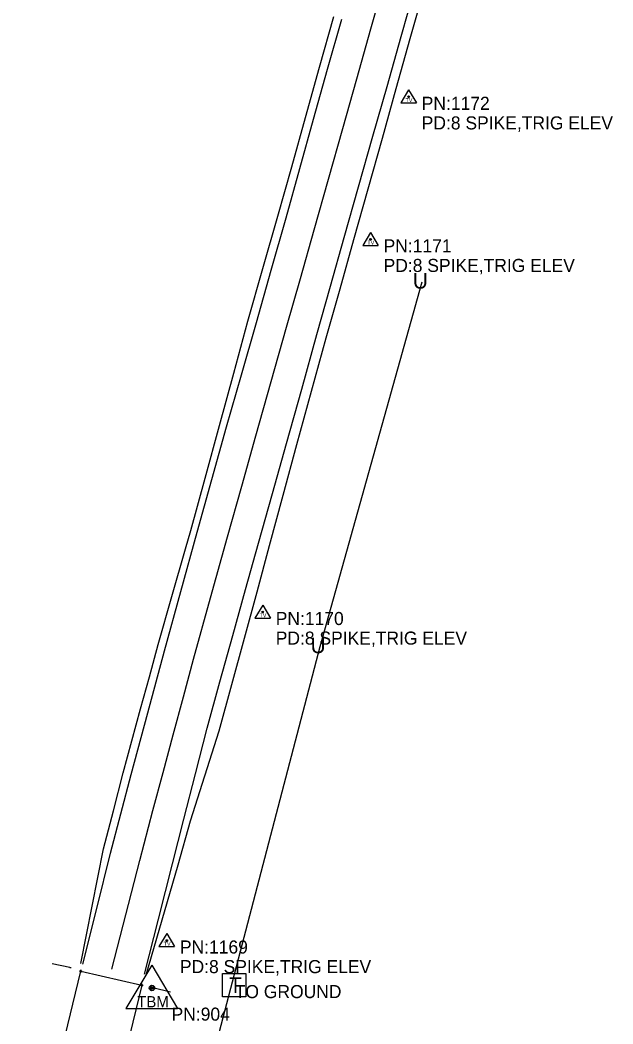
# Model space of a CAD drawing. Extents: x 1445297 to 1476720, y 2042269 to 2057889.
# Drawn here: x 1445820.8 to 1446047.7, y 2054654 to 2055038.2 of the extents above; entities that cross this region are included whole.
import ezdxf

# ---------------------------------------------------------------- set-up
doc = ezdxf.new("R2010")
doc.units = 0
for name, color, linetype in [('S_BRIDGE', 7, 'Continuous'), ('S_EDGE_PAVEMENT', 7, 'Continuous'), ('S_PAVEMENT_CROWN', 7, 'Continuous'), ('S_PRIMARY_CTL', 7, 'Continuous'), ('S_PRIMARY_CTL_ANNOT', 7, 'Continuous'), ('S_SECONDARY_CTL', 7, 'Continuous'), ('S_SECONDARY_CTL_ANNOT', 7, 'Continuous'), ('S_SHOULDER', 7, 'Continuous'), ('S_STR_PT_SYM', 7, 'Continuous'), ('S_TELEPHONE_UTILITIES', 7, 'Continuous'), ('S_TELEPHONE_UTILITIES_ANNOT', 7, 'Continuous'), ('S_UNDERGROUND_CABLE', 7, 'Continuous'), ('S_UTL_PT_SYM', 7, 'Continuous'), ('S_WALL', 7, 'Continuous')]:
    doc.layers.add(name, color=color, linetype=linetype)

msp = doc.modelspace()

# ---------------------------------------------------------------- linework, layer by layer
at = {"layer": 'S_BRIDGE'}
for p, q in [((1445820.81, 2054577.05), (1445844.02, 2054674.24)), ((1445844.02, 2054674.24), (1445867.36, 2054668.87)), ((1445867.36, 2054668.87), (1445844.01, 2054571.43))]:
    msp.add_line(p, q, dxfattribs=at)
at = {"layer": 'S_EDGE_PAVEMENT'}
for points in [[(1445868.42, 2054673), (1445873.8, 2054694.15), (1445879.18, 2054715.3), (1445883.43, 2054732.32), (1445887.92, 2054749.76), (1445892.4, 2054767.2), (1445897.32, 2054784.9), (1445902.23, 2054802.61), (1445907.14, 2054820.31), (1445912.06, 2054838.01), (1445917.42, 2054857.06), (1445922.78, 2054876.11), (1445928.6, 2054897), (1445934.41, 2054917.89), (1445939.66, 2054936.42), (1445944.91, 2054954.95), (1445950.38, 2054974.34), (1445955.85, 2054993.73), (1445961.24, 2055012.84), (1445966.63, 2055031.96), (1445972, 2055050.98)], [(1445844.89, 2054676.9), (1445850.15, 2054698.12), (1445855.4, 2054719.34), (1445859.33, 2054734.41), (1445863.27, 2054749.48), (1445869.68, 2054773.13), (1445876.1, 2054796.78), (1445882.33, 2054819.51), (1445888.57, 2054842.24), (1445894.2, 2054862.4), (1445899.83, 2054882.56), (1445905.54, 2054902.48), (1445911.24, 2054922.4), (1445916.92, 2054942.47), (1445922.59, 2054962.55), (1445927.86, 2054981.39), (1445933.14, 2055000.23), (1445938.52, 2055019.41), (1445943.91, 2055038.59)]]:
    msp.add_lwpolyline(points, dxfattribs=at)
at = {"layer": 'S_PAVEMENT_CROWN'}
msp.add_lwpolyline([(1445855.91, 2054675.01), (1445861.26, 2054695.81), (1445866.61, 2054716.61), (1445871.67, 2054735.74), (1445875.56, 2054750.21), (1445879.46, 2054764.68), (1445883.35, 2054779.16), (1445887.24, 2054793.63), (1445893.7, 2054817.03), (1445900.17, 2054840.42), (1445905.62, 2054859.76), (1445911.06, 2054879.11), (1445916.95, 2054899.9), (1445922.84, 2054920.69), (1445928.1, 2054939.34), (1445933.36, 2054957.99), (1445938.82, 2054977.34), (1445944.28, 2054996.69), (1445949.66, 2055015.74), (1445955.04, 2055034.8), (1445960.36, 2055053.8)], dxfattribs=at)
at = {"layer": 'S_PRIMARY_CTL'}
for p, q in [((1445871.29, 2054676.45), (1445861.26, 2054659.94)), ((1445871.29, 2054676.45), (1445881.11, 2054659.94)), ((1445861.26, 2054659.94), (1445881.11, 2054659.94))]:
    msp.add_line(p, q, dxfattribs=at)
for radius in [1.04, 0.609, 0.344]:
    msp.add_circle((1445871.29, 2054667.75), radius, dxfattribs=at)
at = {"layer": 'S_SECONDARY_CTL'}
for p, q in [((1445969.53, 2055011.46), (1445966.52, 2055006.51)), ((1445969.53, 2055011.46), (1445972.48, 2055006.51)), ((1445966.52, 2055006.51), (1445972.48, 2055006.51)), ((1445954.94, 2054956.91), (1445951.93, 2054951.96)), ((1445954.94, 2054956.91), (1445957.89, 2054951.96)), ((1445951.93, 2054951.96), (1445957.89, 2054951.96)), ((1445913.66, 2054814.28), (1445910.65, 2054809.33)), ((1445913.66, 2054814.28), (1445916.61, 2054809.33)), ((1445910.65, 2054809.33), (1445916.61, 2054809.33)), ((1445876.98, 2054688.55), (1445873.97, 2054683.6)), ((1445876.98, 2054688.55), (1445879.93, 2054683.6)), ((1445873.97, 2054683.6), (1445879.93, 2054683.6))]:
    msp.add_line(p, q, dxfattribs=at)
for centre, radius in [((1445969.53, 2055008.85), 0.311), ((1445969.53, 2055008.85), 0.183), ((1445969.53, 2055008.85), 0.103), ((1445954.94, 2054954.3), 0.311), ((1445954.94, 2054954.3), 0.183), ((1445954.94, 2054954.3), 0.103), ((1445913.66, 2054811.67), 0.311), ((1445913.66, 2054811.67), 0.183), ((1445913.66, 2054811.67), 0.103), ((1445876.98, 2054685.94), 0.311), ((1445876.98, 2054685.94), 0.183), ((1445876.98, 2054685.94), 0.103)]:
    msp.add_circle(centre, radius, dxfattribs=at)
at = {"layer": 'S_SHOULDER'}
for points in [[(1445869.12, 2054672.84), (1445875.24, 2054693.88), (1445881.35, 2054714.93), (1445886.02, 2054731.75), (1445891.55, 2054748.94), (1445897.07, 2054766.13), (1445901.88, 2054783.86), (1445906.68, 2054801.6), (1445911.49, 2054819.33), (1445916.29, 2054837.07), (1445921.52, 2054856.42), (1445926.74, 2054875.78), (1445932.37, 2054896.18), (1445938, 2054916.58), (1445943.3, 2054935.38), (1445948.6, 2054954.19), (1445954.03, 2054973.6), (1445959.46, 2054993.01), (1445964.77, 2055012.06), (1445970.08, 2055031.1), (1445975.49, 2055050.1)], [(1445844.07, 2054677.1), (1445848.4, 2054699.06), (1445852.73, 2054721.02), (1445856.51, 2054735.58), (1445860.29, 2054750.14), (1445863.63, 2054762.4), (1445866.96, 2054774.66), (1445870.3, 2054786.91), (1445873.64, 2054799.17), (1445878.88, 2054817.53), (1445884.12, 2054835.89), (1445886.15, 2054842.8), (1445891.63, 2054862.92), (1445897.1, 2054883.04), (1445902.57, 2054903.02), (1445908.04, 2054922.99), (1445913.77, 2054943.1), (1445919.49, 2054963.22), (1445924.78, 2054982.04), (1445930.06, 2055000.86), (1445935.44, 2055020.19), (1445940.83, 2055039.53)]]:
    msp.add_lwpolyline(points, dxfattribs=at)
at = {"layer": 'S_STR_PT_SYM'}
for points in [[(1445844.02, 2054674.24), (1445844.02, 2054674.74), (1445844.02, 2054674.24), (1445843.52, 2054674.24), (1445844.02, 2054674.24), (1445844.02, 2054673.74), (1445844.02, 2054674.24), (1445844.52, 2054674.24)], [(1445867.36, 2054668.87), (1445867.36, 2054669.37), (1445867.36, 2054668.87), (1445866.86, 2054668.87), (1445867.36, 2054668.87), (1445867.36, 2054668.37), (1445867.36, 2054668.87), (1445867.86, 2054668.87)]]:
    msp.add_lwpolyline(points, dxfattribs=at)
at = {"layer": 'S_TELEPHONE_UTILITIES'}
msp.add_lwpolyline([(1445898.23, 2054664.36), (1445898.23, 2054673.36), (1445907.23, 2054673.36), (1445907.23, 2054664.36)], close=True, dxfattribs=at)
at = {"layer": 'S_UNDERGROUND_CABLE'}
for p, q in [((1445935.62, 2054798.44), (1445974.75, 2054937.98)), ((1445870.09, 2054547.32), (1445935.62, 2054798.44))]:
    msp.add_line(p, q, dxfattribs=at)
at = {"layer": 'S_WALL'}
for points in [[(1445840.34, 2054675.43), (1445839.99, 2054675.52), (1445839.81, 2054675.54), (1445833.07, 2054676.94)], [(1445871.03, 2054668.15), (1445871.46, 2054668.1), (1445871.64, 2054667.94), (1445878.42, 2054666.24)]]:
    msp.add_lwpolyline(points, dxfattribs=at)

# ---------------------------------------------------------------- texts
at = {"layer": 'S_PRIMARY_CTL'}
msp.add_text('TBM', height=4.287, dxfattribs=at).set_placement((1445865.64, 2054660.36))
at = {"layer": 'S_PRIMARY_CTL_ANNOT'}
msp.add_text('PN:904', height=5, dxfattribs=at).set_placement((1445878.79, 2054655.25))
at = {"layer": 'S_SECONDARY_CTL'}
for p in [(1445968.33, 2055006.84), (1445953.74, 2054952.29), (1445912.46, 2054809.66), (1445875.78, 2054683.93)]:
    msp.add_text('TV', height=1.5, dxfattribs=at).set_placement(p)
at = {"layer": 'S_SECONDARY_CTL_ANNOT'}
for s, p in [('PN:1172', (1445974.53, 2055003.85)), ('PD:8 SPIKE,TRIG ELEV', (1445974.53, 2054996.35)), ('PN:1171', (1445959.94, 2054949.3)), ('PD:8 SPIKE,TRIG ELEV', (1445959.94, 2054941.8)), ('PN:1170', (1445918.66, 2054806.67)), ('PD:8 SPIKE,TRIG ELEV', (1445918.66, 2054799.17)), ('PN:1169', (1445881.98, 2054680.94)), ('PD:8 SPIKE,TRIG ELEV', (1445881.98, 2054673.44))]:
    msp.add_text(s, height=5, dxfattribs=at).set_placement(p)
at = {"layer": 'S_TELEPHONE_UTILITIES'}
msp.add_text('T', height=6, dxfattribs=at).set_placement((1445900.8, 2054665.86))
at = {"layer": 'S_TELEPHONE_UTILITIES_ANNOT'}
msp.add_text('TO GROUND', height=5, dxfattribs=at).set_placement((1445902.96, 2054663.88))
at = {"layer": 'S_UTL_PT_SYM'}
for p in [(1445971.12, 2054935.43), (1445931.99, 2054795.9)]:
    msp.add_text('U', height=6, dxfattribs=at).set_placement(p)

doc.saveas('drawing.dxf')
